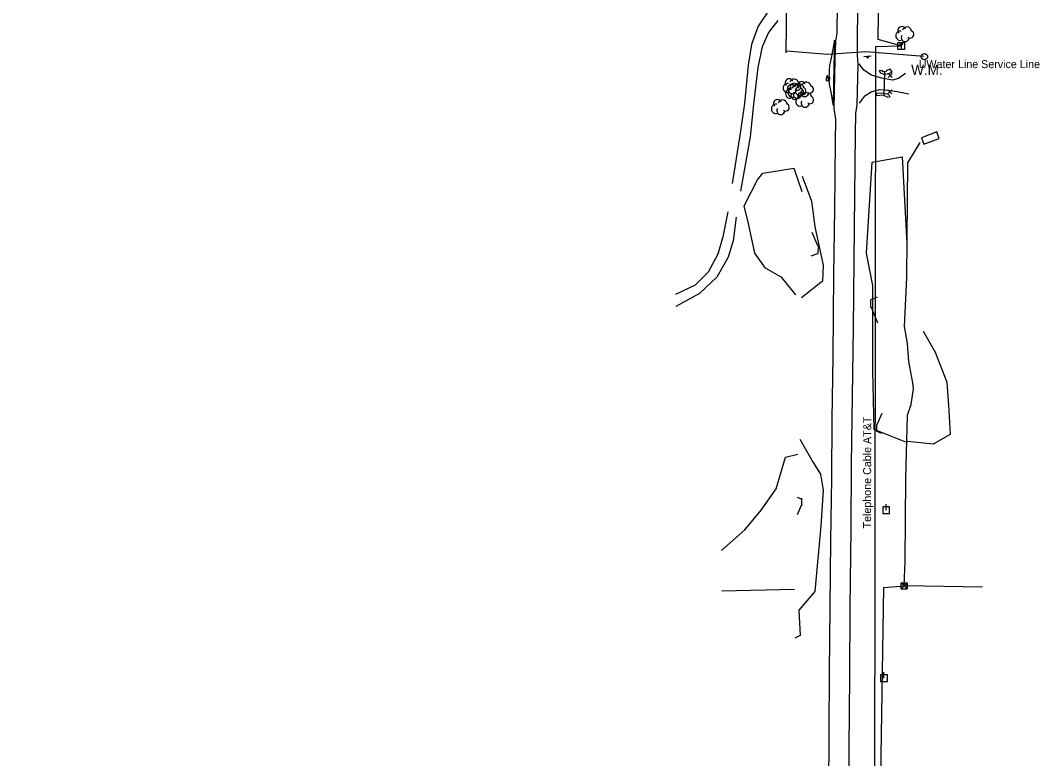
# Model space of a CAD drawing. Extents: x 19405533 to 19432306, y 137070 to 200991.
# Drawn here: x 19423179 to 19424370, y 152983 to 153845 of the extents above; entities that cross this region are included whole.
import ezdxf

# ---------------------------------------------------------------- set-up
doc = ezdxf.new("R2010")
doc.units = 0
for name, color, linetype in [('sv_Bituminous Area_x_s', 7, 'Continuous'), ('sv_Drainage Structures_x_s', 7, 'Continuous'), ('sv_Fence Existing_x_s', 7, 'Continuous'), ('sv_Mailbox_x_n', 7, 'Continuous'), ('sv_Pavement Edge_x_s', 7, 'Continuous'), ('sv_Poles Utility_x_n', 7, 'Continuous'), ('sv_Private Road_x_s', 7, 'Continuous'), ('sv_Rip Rap_x_s', 7, 'Continuous'), ('sv_RW Marker_x_n', 7, 'Continuous'), ('sv_Signs Billboards_x_s', 7, 'Continuous'), ('sv_Telephone Line Label_x_n', 7, 'Continuous'), ('sv_Telephone Line_x_n', 7, 'Continuous'), ('sv_Tree Bush_x_s', 7, 'Continuous'), ('sv_Treeline_x_s', 7, 'Continuous'), ('sv_Water Line Label_x_n', 7, 'Continuous'), ('sv_Water Line_x_n', 7, 'Continuous')]:
    doc.layers.add(name, color=color, linetype=linetype)

msp = doc.modelspace()

# ---------------------------------------------------------------- linework, layer by layer
at = {"layer": 'sv_Bituminous Area_x_s'}
msp.add_lwpolyline([(19424130.6, 153822.2), (19424126.3, 153799.4), (19424124.9, 153793.3), (19424124.2, 153787), (19424124.1, 153776.4), (19424124.5, 153770.9), (19424126.4, 153761.9), (19424128.6, 153747.2), (19424129.5, 153746), (19424129.9, 153770.9), (19424130.2, 153792), (19424130.9, 153817.8), (19424130.6, 153822.2)], dxfattribs=at)
at = {"layer": 'sv_Drainage Structures_x_s'}
msp.add_line((19424188.7, 153756.9), (19424189.5, 153785.6), dxfattribs=at)
msp.add_line((19424188.7, 153756.9), (19424189.5, 153785.6), dxfattribs=at)
msp.add_line((19424188.7, 153756.9), (19424189.5, 153785.6), dxfattribs=at)
msp.add_line((19424188.7, 153756.9), (19424189.5, 153785.6), dxfattribs=at)
for points in [[(19424103.4, 153570.3), (19424111.3, 153573.2), (19424111.7, 153572.6), (19424111.9, 153582.7), (19424111.3, 153582.2), (19424104.5, 153597.8)], [(19424181.1, 153491.7), (19424174, 153510.1), (19424173.2, 153510.1), (19424173.1, 153519.1), (19424173.6, 153519.3), (19424180.9, 153522.4)], [(19424181.1, 153491.7), (19424174, 153510.1), (19424173.2, 153510.1), (19424173.1, 153519.1), (19424173.6, 153519.3), (19424180.9, 153522.4)], [(19424181.1, 153491.7), (19424174, 153510.1), (19424173.2, 153510.1), (19424173.1, 153519.1), (19424173.6, 153519.3), (19424180.9, 153522.4)], [(19424181.1, 153491.7), (19424174, 153510.1), (19424173.2, 153510.1), (19424173.1, 153519.1), (19424173.6, 153519.3), (19424180.9, 153522.4)], [(19424185.6, 153362.6), (19424180.6, 153365.1), (19424180, 153365.2), (19424180.1, 153372.9), (19424180.3, 153373.1), (19424186.4, 153386.4)], [(19424185.6, 153362.6), (19424180.6, 153365.1), (19424180, 153365.2), (19424180.1, 153372.9), (19424180.3, 153373.1), (19424186.4, 153386.4)], [(19424185.6, 153362.6), (19424180.6, 153365.1), (19424180, 153365.2), (19424180.1, 153372.9), (19424180.3, 153373.1), (19424186.4, 153386.4)], [(19424185.6, 153362.6), (19424180.6, 153365.1), (19424180, 153365.2), (19424180.1, 153372.9), (19424180.3, 153373.1), (19424186.4, 153386.4)], [(19424086.9, 153288.5), (19424091.7, 153286.5), (19424092.1, 153287.2), (19424092.1, 153278.3), (19424091.7, 153278.5), (19424087, 153267.6)]]:
    msp.add_lwpolyline(points, dxfattribs=at)
at = {"layer": 'sv_Fence Existing_x_s'}
for p, q in [((19424193.4, 153778.7), (19424198.1, 153783.5)), ((19424193.4, 153783.5), (19424198.1, 153778.7)), ((19424192.9, 153759.6), (19424197.6, 153764.3)), ((19424192.9, 153764.3), (19424197.6, 153759.6)), ((19424084, 153180.3), (19423999.1, 153178.4)), ((19424303.4, 153183.2), (19424212.7, 153184.8))]:
    msp.add_line(p, q, dxfattribs=at)
msp.add_lwpolyline([(19424198.7, 152680.8), (19424183.3, 152684.4), (19424183.1, 152748.8), (19424185.3, 152986.5), (19424188.4, 153183), (19424212, 153184.9), (19424213, 153213.7), (19424213.9, 153310.2), (19424216, 153384.2), (19424220.2, 153396.8), (19424222.9, 153414.8), (19424222.1, 153422.1), (19424217.6, 153446.8), (19424215.8, 153468.1), (19424212.3, 153487.8), (19424212.3, 153487.7), (19424215.1, 153545.2), (19424216.4, 153679.1), (19424230.5, 153702.8)], dxfattribs=at)
msp.add_lwpolyline([(19424198.7, 152680.8), (19424183.3, 152684.4), (19424183.1, 152748.8), (19424185.3, 152986.5), (19424188.4, 153183), (19424212, 153184.9), (19424213, 153213.7), (19424213.9, 153310.2), (19424216, 153384.2), (19424220.2, 153396.8), (19424222.9, 153414.8), (19424222.1, 153422.1), (19424217.6, 153446.8), (19424215.8, 153468.1), (19424212.3, 153487.8), (19424212.3, 153487.7), (19424215.1, 153545.2), (19424216.4, 153679.1), (19424230.5, 153702.8)], dxfattribs=at)
msp.add_lwpolyline([(19424198.7, 152680.8), (19424183.3, 152684.4), (19424183.1, 152748.8), (19424185.3, 152986.5), (19424188.4, 153183), (19424212, 153184.9), (19424213, 153213.7), (19424213.9, 153310.2), (19424216, 153384.2), (19424220.2, 153396.8), (19424222.9, 153414.8), (19424222.1, 153422.1), (19424217.6, 153446.8), (19424215.8, 153468.1), (19424212.3, 153487.8), (19424212.3, 153487.7), (19424215.1, 153545.2), (19424216.4, 153679.1), (19424230.5, 153702.8)], dxfattribs=at)
msp.add_lwpolyline([(19424198.7, 152680.8), (19424183.3, 152684.4), (19424183.1, 152748.8), (19424185.3, 152986.5), (19424188.4, 153183), (19424212, 153184.9), (19424213, 153213.7), (19424213.9, 153310.2), (19424216, 153384.2), (19424220.2, 153396.8), (19424222.9, 153414.8), (19424222.1, 153422.1), (19424217.6, 153446.8), (19424215.8, 153468.1), (19424212.3, 153487.8), (19424212.3, 153487.7), (19424215.1, 153545.2), (19424216.4, 153679.1), (19424230.5, 153702.8)], dxfattribs=at)
at = {"layer": 'sv_Mailbox_x_n'}
msp.add_lwpolyline([(19424121.6, 153778.7), (19424121.7, 153778.8), (19424122, 153778.8), (19424122.4, 153778.7), (19424122.8, 153778.3), (19424123, 153777.6), (19424123.1, 153776.9), (19424123.1, 153774.8), (19424125.3, 153776.4), (19424125.3, 153777.6), (19424125.3, 153778), (19424125.1, 153778.7), (19424125, 153779), (19424124.7, 153779.4), (19424124.5, 153779.5), (19424124.2, 153779.5), (19424122, 153778.8), (19424121.7, 153778.8), (19424121.7, 153779.8), (19424122.4, 153780), (19424122.4, 153781), (19424121.6, 153780.8), (19424121.6, 153778.7), (19424121.3, 153778.3), (19424121, 153777.6), (19424120.9, 153776.9), (19424120.9, 153775.1), (19424123.1, 153774.8)], dxfattribs=at)
msp.add_lwpolyline([(19424121.6, 153778.7), (19424121.7, 153778.8), (19424122, 153778.8), (19424122.4, 153778.7), (19424122.8, 153778.3), (19424123, 153777.6), (19424123.1, 153776.9), (19424123.1, 153774.8), (19424125.3, 153776.4), (19424125.3, 153777.6), (19424125.3, 153778), (19424125.1, 153778.7), (19424125, 153779), (19424124.7, 153779.4), (19424124.5, 153779.5), (19424124.2, 153779.5), (19424122, 153778.8), (19424121.7, 153778.8), (19424121.7, 153779.8), (19424122.4, 153780), (19424122.4, 153781), (19424121.6, 153780.8), (19424121.6, 153778.7), (19424121.3, 153778.3), (19424121, 153777.6), (19424120.9, 153776.9), (19424120.9, 153775.1), (19424123.1, 153774.8)], dxfattribs=at)
at = {"layer": 'sv_Pavement Edge_x_s'}
for points in [[(19424157.4, 153876.6), (19424157, 153804.7), (19424158, 153793.9), (19424156.5, 153746.9), (19424155, 153736.6), (19424154.9, 153712.9), (19424154, 153641.7), (19424153.1, 153564), (19424152.3, 153486.3), (19424151.2, 153406.2), (19424150.2, 153326.8), (19424149.5, 153251.1), (19424148.7, 153159.7), (19424148.1, 153078.9), (19424147.3, 152995.8), (19424146.8, 152909.7), (19424146.1, 152841.5), (19424146, 152796.5)], [(19424122.1, 152797.8), (19424123, 152871.3), (19424123.8, 152943.3), (19424124.4, 153014.5), (19424124.9, 153084.3), (19424125.7, 153160.3), (19424126.5, 153237.7), (19424127.3, 153310.3), (19424128, 153379.6), (19424129.2, 153453.2), (19424130, 153548.4), (19424131, 153624.4), (19424131.9, 153703.4), (19424132.3, 153730), (19424130.3, 153742.4), (19424131.5, 153800), (19424132.3, 153821.3), (19424133.7, 153830.5), (19424134.1, 153863.5)]]:
    msp.add_lwpolyline(points, dxfattribs=at)
at = {"layer": 'sv_Poles Utility_x_n'}
for p, q in [((19424191, 153273.3), (19424191, 153280.3)), ((19424187, 153277.1), (19424187.1, 153277.2)), ((19424184.4, 153080.7), (19424184.5, 153080.8)), ((19424188.4, 153076.9), (19424188.4, 153083.9))]:
    msp.add_line(p, q, dxfattribs=at)
for points in [[(19424187, 153269.2), (19424195, 153269.2), (19424195, 153277.2), (19424187, 153277.2)], [(19424184.4, 153072.8), (19424192.4, 153072.8), (19424192.4, 153080.8), (19424184.4, 153080.8)]]:
    msp.add_lwpolyline(points, close=True, dxfattribs=at)
at = {"layer": 'sv_Private Road_x_s'}
for points in [[(19424053.3, 153856.5), (19424041.5, 153838.8), (19424033.5, 153817.3), (19424029.6, 153793.3), (19424025.4, 153748.3), (19424020.1, 153711), (19424011.2, 153654.8)], [(19424064.2, 153845.3), (19424053.6, 153831.4), (19424046.2, 153814.7), (19424041.2, 153790.3), (19424036.1, 153747.7), (19424032, 153709.6), (19424020.9, 153646)], [(19424213.4, 153783.3), (19424205.5, 153777.7), (19424198.3, 153775.7), (19424185.4, 153777.8), (19424173.7, 153781.3), (19424164.8, 153787.4), (19424159.5, 153794.7)], [(19424213.4, 153783.3), (19424205.5, 153777.7), (19424198.3, 153775.7), (19424185.4, 153777.8), (19424173.7, 153781.3), (19424164.8, 153787.4), (19424159.5, 153794.7)], [(19424213.4, 153783.3), (19424205.5, 153777.7), (19424198.3, 153775.7), (19424185.4, 153777.8), (19424173.7, 153781.3), (19424164.8, 153787.4), (19424159.5, 153794.7)], [(19424213.4, 153783.3), (19424205.5, 153777.7), (19424198.3, 153775.7), (19424185.4, 153777.8), (19424173.7, 153781.3), (19424164.8, 153787.4), (19424159.5, 153794.7)], [(19424217.6, 153759.1), (19424203.8, 153761.9), (19424189.8, 153764), (19424183.2, 153764.4), (19424174.1, 153762.1), (19424165.1, 153756.5), (19424159.3, 153748.7)], [(19424217.6, 153759.1), (19424203.8, 153761.9), (19424189.8, 153764), (19424183.2, 153764.4), (19424174.1, 153762.1), (19424165.1, 153756.5), (19424159.3, 153748.7)], [(19424217.6, 153759.1), (19424203.8, 153761.9), (19424189.8, 153764), (19424183.2, 153764.4), (19424174.1, 153762.1), (19424165.1, 153756.5), (19424159.3, 153748.7)], [(19424217.6, 153759.1), (19424203.8, 153761.9), (19424189.8, 153764), (19424183.2, 153764.4), (19424174.1, 153762.1), (19424165.1, 153756.5), (19424159.3, 153748.7)], [(19424234.8, 153700.8), (19424252.8, 153707.6), (19424250.3, 153715.1), (19424232.2, 153708.3), (19424234.8, 153700.8)], [(19424006.1, 153621.6), (19424000.3, 153592.6), (19423994.4, 153572.2), (19423983, 153551.4), (19423967.7, 153535.9), (19423945, 153525.1)], [(19424015.7, 153615.6), (19424012.3, 153587.9), (19424006.3, 153568.9), (19423993, 153545.4), (19423972.9, 153526.5), (19423945.2, 153511.1)]]:
    msp.add_lwpolyline(points, dxfattribs=at)
at = {"layer": 'sv_Rip Rap_x_s'}
for points in [[(19424182.9, 153786.9), (19424184.3, 153784.3), (19424187.8, 153782.8), (19424192.5, 153783.2), (19424198, 153785.1), (19424195.5, 153788.3), (19424191.4, 153786.8), (19424191.1, 153785.9), (19424187.5, 153785.4), (19424186.5, 153786.7), (19424182.9, 153786.9)], [(19424182.9, 153786.9), (19424184.3, 153784.3), (19424187.8, 153782.8), (19424192.5, 153783.2), (19424198, 153785.1), (19424195.5, 153788.3), (19424191.4, 153786.8), (19424191.1, 153785.9), (19424187.5, 153785.4), (19424186.5, 153786.7), (19424182.9, 153786.9)], [(19424182.9, 153786.9), (19424184.3, 153784.3), (19424187.8, 153782.8), (19424192.5, 153783.2), (19424198, 153785.1), (19424195.5, 153788.3), (19424191.4, 153786.8), (19424191.1, 153785.9), (19424187.5, 153785.4), (19424186.5, 153786.7), (19424182.9, 153786.9)], [(19424182.9, 153786.9), (19424184.3, 153784.3), (19424187.8, 153782.8), (19424192.5, 153783.2), (19424198, 153785.1), (19424195.5, 153788.3), (19424191.4, 153786.8), (19424191.1, 153785.9), (19424187.5, 153785.4), (19424186.5, 153786.7), (19424182.9, 153786.9)], [(19424180, 153757.4), (19424179.4, 153760.7), (19424188.8, 153760.5), (19424193.7, 153759.3), (19424195.4, 153756.3), (19424193.2, 153755.4), (19424191.1, 153756.6), (19424187, 153758.1), (19424180, 153757.4)], [(19424180, 153757.4), (19424179.4, 153760.7), (19424188.8, 153760.5), (19424193.7, 153759.3), (19424195.4, 153756.3), (19424193.2, 153755.4), (19424191.1, 153756.6), (19424187, 153758.1), (19424180, 153757.4)], [(19424180, 153757.4), (19424179.4, 153760.7), (19424188.8, 153760.5), (19424193.7, 153759.3), (19424195.4, 153756.3), (19424193.2, 153755.4), (19424191.1, 153756.6), (19424187, 153758.1), (19424180, 153757.4)], [(19424180, 153757.4), (19424179.4, 153760.7), (19424188.8, 153760.5), (19424193.7, 153759.3), (19424195.4, 153756.3), (19424193.2, 153755.4), (19424191.1, 153756.6), (19424187, 153758.1), (19424180, 153757.4)]]:
    msp.add_lwpolyline(points, dxfattribs=at)
at = {"layer": 'sv_RW Marker_x_n'}
msp.add_lwpolyline([(19424208.5, 153181.2), (19424208.5, 153188.2), (19424215.6, 153188.2), (19424208.5, 153181.2), (19424215.6, 153181.2), (19424215.6, 153188.2), (19424215.6, 153181.2), (19424208.5, 153188.2)], dxfattribs=at)
at = {"layer": 'sv_Signs Billboards_x_s'}
msp.add_line((19424173.5, 153803.6), (19424164.7, 153802.9), dxfattribs=at)
msp.add_circle((19424169.2, 153802.4), 0.885, dxfattribs=at)
at = {"layer": 'sv_Telephone Line_x_n'}
for points in [[(19424178.9, 152524.1), (19424177.2, 152639.3), (19424179, 153815.1), (19424208.2, 153815.7), (19424181.8, 153823.2), (19424195.8, 154938.9), (19424203.9, 154944.6), (19424194.7, 154948.5), (19424203.7, 155703.9), (19424211.3, 155710.3), (19424203.2, 155713.2), (19424208.2, 156250.3), (19424216.1, 156255), (19424209.4, 156263.3), (19424211.5, 156932.7), (19424190.3, 156958.5), (19424190.8, 156972.3), (19424219.1, 157002.4), (19424235.5, 158756.3), (19424249.1, 160231.2), (19424255.5, 160239.3), (19424256.2, 160264), (19424249, 160267.4), (19424266.1, 161627.2)], [(19424206.4, 153817.7), (19424210.4, 153817.7), (19424208.4, 153817.7), (19424208.4, 153811.5), (19424204.4, 153811.5), (19424204.4, 153819.5), (19424212.4, 153819.5), (19424212.4, 153811.5), (19424208.4, 153811.5)]]:
    msp.add_lwpolyline(points, dxfattribs=at)
at = {"layer": 'sv_Tree Bush_x_s'}
for p, q in [((19424212.8, 153830.6), (19424212.8, 153830.6)), ((19424081, 153769.6), (19424081, 153769.6)), ((19424083.9, 153763.1), (19424083.9, 153763.1)), ((19424086.8, 153764.4), (19424086.8, 153764.4)), ((19424095.5, 153766.3), (19424095.5, 153766.3)), ((19424067.4, 153745.3), (19424067.4, 153745.3)), ((19424095.8, 153753.9), (19424095.8, 153753.9))]:
    msp.add_line(p, q, dxfattribs=at)
for centre, radius, start, end in [((19424207.6, 153827.5), 5.38, 79.5088, 280.4912), ((19424209.3, 153833.6), 4.64, 24.3415, 220.6005), ((19424215.2, 153832.3), 5.51, 12.1303, 160.2411), ((19424218.9, 153829.2), 4.35, 234.1223, 76.9895), ((19424213.2, 153825.3), 4.6, 147.5287, 355.6007), ((19424075.8, 153766.4), 5.38, 79.5088, 280.4912), ((19424077.5, 153772.6), 4.64, 24.3415, 220.6005), ((19424080.4, 153766.1), 4.64, 24.3415, 220.6005), ((19424083.4, 153771.3), 5.51, 12.1303, 160.2411), ((19424083.3, 153767.4), 4.64, 24.3415, 220.6005), ((19424086.3, 153764.8), 5.51, 12.1303, 160.2411), ((19424089.2, 153766), 5.51, 12.1303, 160.2411), ((19424087.1, 153768.2), 4.35, 234.1223, 76.9895), ((19424090.3, 153763.1), 5.38, 79.5088, 280.4912), ((19424092, 153769.3), 4.64, 24.3415, 220.6005), ((19424097.9, 153767.9), 5.51, 12.1303, 160.2411), ((19424101.6, 153764.9), 4.35, 234.1223, 76.9895), ((19424078.7, 153759.9), 5.38, 79.5088, 280.4912), ((19424081.6, 153761.2), 5.38, 79.5088, 280.4912), ((19424081.4, 153764.3), 4.6, 147.5287, 355.6007), ((19424084.3, 153757.8), 4.6, 147.5287, 355.6007), ((19424087.2, 153759.1), 4.6, 147.5287, 355.6007), ((19424090, 153761.7), 4.35, 234.1223, 76.9895), ((19424092.3, 153756.9), 4.64, 24.3415, 220.6005), ((19424092.9, 153763), 4.35, 234.1223, 76.9895), ((19424095.9, 153761), 4.6, 147.5287, 355.6007), ((19424098.2, 153755.5), 5.51, 12.1303, 160.2411), ((19424101.9, 153752.5), 4.35, 234.1223, 76.9895), ((19424062.2, 153742.1), 5.38, 79.5088, 280.4912), ((19424063.9, 153748.3), 4.64, 24.3415, 220.6005), ((19424069.8, 153747), 5.51, 12.1303, 160.2411), ((19424073.5, 153743.9), 4.35, 234.1223, 76.9895), ((19424090.6, 153750.7), 5.38, 79.5088, 280.4912), ((19424096.2, 153748.6), 4.6, 147.5287, 355.6007), ((19424067.8, 153740), 4.6, 147.5287, 355.6007)]:
    msp.add_arc(centre, radius, start, end, dxfattribs=at)
at = {"layer": 'sv_Treeline_x_s'}
for points in [[(19424213.8, 153352.8), (19424177, 153367.4), (19424175.3, 153435.8), (19424175.5, 153535.8), (19424167.8, 153573.5), (19424174.5, 153679.7), (19424209.7, 153686.1), (19424215.3, 153584.7)], [(19424213.8, 153352.8), (19424177, 153367.4), (19424175.3, 153435.8), (19424175.5, 153535.8), (19424167.8, 153573.5), (19424174.5, 153679.7), (19424209.7, 153686.1), (19424215.3, 153584.7)], [(19424213.8, 153352.8), (19424177, 153367.4), (19424175.3, 153435.8), (19424175.5, 153535.8), (19424167.8, 153573.5), (19424174.5, 153679.7), (19424209.7, 153686.1), (19424215.3, 153584.7)], [(19424213.8, 153352.8), (19424177, 153367.4), (19424175.3, 153435.8), (19424175.5, 153535.8), (19424167.8, 153573.5), (19424174.5, 153679.7), (19424209.7, 153686.1), (19424215.3, 153584.7)], [(19424085.4, 153524.9), (19424069, 153545), (19424049.9, 153555.8), (19424037.4, 153573.3), (19424030.2, 153608.3), (19424024.9, 153628.9), (19424040.8, 153659.2), (19424047, 153666.8), (19424083, 153672.8), (19424092.4, 153645.6)], [(19424093, 153663.5), (19424103.9, 153634.3), (19424107.6, 153604.3), (19424117.4, 153559.4), (19424116.7, 153540.9), (19424091.9, 153521.2)], [(19424234.3, 153482.4), (19424248.3, 153457.8), (19424262, 153422.9), (19424264, 153389.5), (19424265.7, 153361.4), (19424245.9, 153350.3), (19424215.8, 153353.3)], [(19424090.2, 153356.3), (19424105.8, 153329), (19424114.4, 153315.3), (19424117.5, 153296.5), (19424114.6, 153254.8), (19424107.7, 153178.2), (19424088.8, 153156.2), (19424090.3, 153126.9), (19424084.2, 153123.7)], [(19423998.5, 153226), (19424025.7, 153250.1), (19424044.9, 153273.1), (19424062.5, 153298.2), (19424073.5, 153335.1), (19424087.6, 153338.8)]]:
    msp.add_lwpolyline(points, dxfattribs=at)
at = {"layer": 'sv_Water Line_x_n'}
for points in [[(19424074.2, 153807.4), (19424086.4, 155206.2), (19424105.1, 156971.2), (19424111.5, 157045.7), (19424109.5, 157198.6), (19424132.4, 159239.9), (19424112.9, 159251.9), (19424117.2, 159290.4), (19424129.9, 159297.7), (19424130.8, 159374.8), (19424149.6, 161142.4), (19424163.1, 163322.5), (19424095.6, 163759.5), (19423907, 164295.4), (19423518.5, 164981.6), (19423522.8, 164989.1), (19423515.5, 165003.5), (19423497.2, 165033), (19423204.7, 165520.6), (19423179.4, 165567.8)], [(19424235.1, 153803.1), (19424167.3, 153808.8), (19424122.7, 153805.8), (19424074.1, 153809.5)]]:
    msp.add_lwpolyline(points, dxfattribs=at)
msp.add_circle((19424235.6, 153803.1), 3.78, dxfattribs=at)

# ---------------------------------------------------------------- texts
at = {"layer": 'sv_Telephone Line Label_x_n'}
msp.add_text('Telephone Cable AT&T', height=9.35, rotation=89.9149, dxfattribs=at).set_placement((19424173.3, 153251.8))
at = {"layer": 'sv_Water Line Label_x_n'}
msp.add_text('ÙWater Line Service Line', height=9.35, dxfattribs=at).set_placement((19424229, 153789.7))
at = {"layer": 'sv_Water Line_x_n'}
msp.add_text('W.M.', height=11.8, dxfattribs=at).set_placement((19424220.2, 153781.8))

doc.saveas('drawing.dxf')
